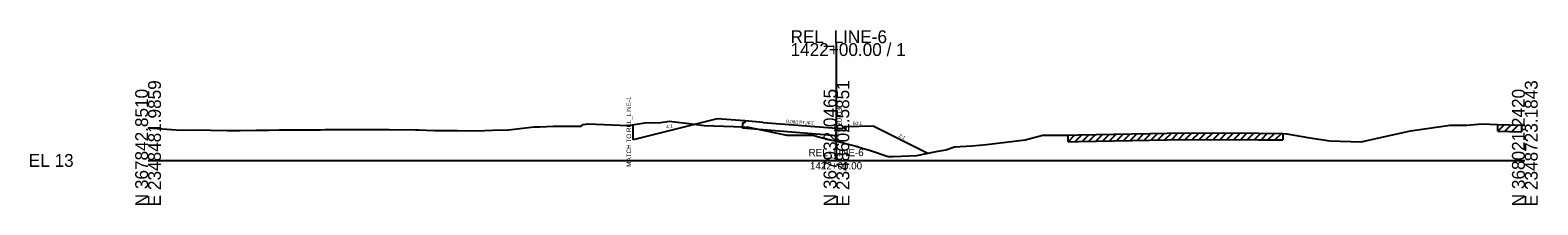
# Model space of a CAD drawing. Extents: x -26 to 403, y -10 to 6565.
# Drawn here: x -25.7 to 302.8, y 2990.3 to 3028.4 of the extents above; entities that cross this region are included whole.
import ezdxf

# ---------------------------------------------------------------- set-up
doc = ezdxf.new("R2010")
doc.units = 0
for name, color, linetype in [('RD_GPK_XS_Cell', 7, 'Continuous'), ('RD_XS_Base', 7, 'Continuous'), ('RD_XS_CurbBase', 7, 'Continuous'), ('RD_XS_CurbFront', 7, 'Continuous'), ('RD_XS_CurbTop', 7, 'Continuous'), ('RD_XS_EarthShd', 7, 'Continuous'), ('RD_XS_ExGround', 7, 'Continuous'), ('RD_XS_ExPaveRet', 7, 'Continuous'), ('RD_XS_Pave', 7, 'Continuous'), ('RD_XS_PaveShd', 7, 'Continuous'), ('RD_XS_TieSlope', 7, 'Continuous'), ('RD_XS_TX_Elev_EX', 7, 'Continuous'), ('RD_XS_TX_Elev_PR', 7, 'Continuous'), ('RD_XS_TX_MatchLine', 7, 'Continuous'), ('RD_XS_TX_Slope', 7, 'Continuous'), ('RD_XS_TX_Station', 7, 'Continuous'), ('RD_XS_TX_TOC', 7, 'Continuous')]:
    doc.layers.add(name, color=color, linetype=linetype)

msp = doc.modelspace()

# ---------------------------------------------------------------- linework, layer by layer
at = {"layer": 'RD_GPK_XS_Cell'}
for p, q in [((150, 3000), (150, 3025.58)), ((0, 3000), (150, 3000)), ((150, 3000), (300, 3000))]:
    msp.add_line(p, q, dxfattribs=at)
at = {"layer": 'RD_XS_Base'}
for p, q in [((130.01, 3008.18), (129.51, 3008.22)), ((129.51, 3008.22), (129.51, 3007.03)), ((150.01, 3005.39), (129.51, 3007.03)), ((130.01, 3008.63), (130.01, 3008.18))]:
    msp.add_line(p, q, dxfattribs=at)
at = {"layer": 'RD_XS_CurbBase'}
for p, q in [((151.51, 3006.43), (150.01, 3006.51)), ((150.01, 3005.39), (150.01, 3006.51)), ((152.01, 3006.43), (151.51, 3006.43)), ((152.01, 3007.43), (152.01, 3006.43))]:
    msp.add_line(p, q, dxfattribs=at)
at = {"layer": 'RD_XS_CurbFront'}
msp.add_line((150.01, 3006.51), (150.01, 3007.01), dxfattribs=at)
at = {"layer": 'RD_XS_CurbTop'}
for p, q in [((150.01, 3007.03), (150.01, 3007.01)), ((150.01, 3007.01), (151.42, 3006.93)), ((151.42, 3006.93), (151.51, 3007.43)), ((151.51, 3007.43), (152.01, 3007.43))]:
    msp.add_line(p, q, dxfattribs=at)
at = {"layer": 'RD_XS_EarthShd'}
for p, q in [((124.01, 3009.11), (105.68, 3004.53)), ((130.01, 3008.63), (124.01, 3009.11)), ((152.01, 3007.43), (158.01, 3007.55))]:
    msp.add_line(p, q, dxfattribs=at)
at = {"layer": 'RD_XS_ExGround'}
msp.add_lwpolyline([(0, 3007.14), (6.15, 3006.7), (8.46, 3006.59), (10.1, 3006.64), (17.24, 3006.5), (20.07, 3006.5), (23.55, 3006.61), (23.86, 3006.61), (24.23, 3006.61), (24.65, 3006.62), (25.13, 3006.62), (25.69, 3006.63), (26.33, 3006.63), (28.56, 3006.64), (29.08, 3006.65), (29.66, 3006.65), (30.33, 3006.66), (31.07, 3006.67), (31.9, 3006.67), (32.81, 3006.68), (33.79, 3006.69), (34.58, 3006.7), (35.48, 3006.7), (35.8, 3006.7), (36.34, 3006.7), (36.92, 3006.71), (37.6, 3006.71), (38.57, 3006.72), (39.79, 3006.72), (40.87, 3006.73), (41.96, 3006.74), (42.63, 3006.75), (43, 3006.76), (43.51, 3006.76), (43.93, 3006.77), (45.04, 3006.78), (45.54, 3006.78), (46.34, 3006.78), (47.07, 3006.78), (47.71, 3006.77), (48.6, 3006.77), (49.4, 3006.77), (50.12, 3006.76), (50.75, 3006.76), (51.31, 3006.75), (51.79, 3006.75), (52.21, 3006.74), (52.56, 3006.73), (58.28, 3006.71), (58.93, 3006.71), (62.45, 3006.53), (67.41, 3006.51), (71.63, 3006.46), (75.05, 3006.63), (78.52, 3006.69), (84.16, 3007.32), (84.56, 3007.33), (84.97, 3007.34), (85.38, 3007.35), (88.33, 3007.49), (91.45, 3007.47), (93.39, 3007.47), (94.36, 3007.47), (94.8, 3007.82), (95.41, 3007.91), (95.82, 3007.97), (104.56, 3007.61), (108.28, 3008.2), (111.76, 3008.31), (113.53, 3008.53), (117.82, 3008.09), (121.21, 3007.65), (127.64, 3007.42), (130.86, 3007.24), (136.33, 3006.08), (137.08, 3005.94), (139.19, 3005.53), (143.23, 3005.52), (144.85, 3005.48), (146.7, 3004.98), (148.62, 3004.52), (150, 3004.17), (154.32, 3003.08), (155.86, 3002.63), (156.7, 3002.42), (157.43, 3002.19), (161.3, 3000.87), (162.41, 3000.89), (167.51, 3001.11), (172.11, 3002.01), (173.84, 3002.3), (175.73, 3002.95), (179.52, 3003.18), (181.15, 3003.3), (182.73, 3003.47), (191.11, 3004.49), (193.32, 3005.08), (194.94, 3005.5), (199.99, 3005.53), (200.52, 3005.53), (202.71, 3005.57), (222.05, 3005.95), (224.62, 3006), (241.99, 3005.92), (247.3, 3005.9), (248.14, 3005.83), (252.75, 3005.03), (257.54, 3004.28), (264.37, 3004.08), (265.31, 3004.29), (275.11, 3006.46), (280.19, 3007.22), (283.77, 3007.72), (287.44, 3007.72), (290.65, 3007.97), (294.15, 3007.86), (299.19, 3007.69), (300, 3007.67)], dxfattribs=at)
at = {"layer": 'RD_XS_ExPaveRet'}
for p, q in [((294.15, 3006.42), (294.15, 3007.86)), ((294.15, 3006.42), (295.54, 3007.81)), ((294.15, 3006.42), (299.19, 3006.25)), ((295.65, 3006.37), (297.04, 3007.76)), ((297.15, 3006.32), (298.54, 3007.71)), ((299.19, 3006.25), (299.28, 3006.25)), ((299.28, 3007.69), (299.28, 3006.25)), ((200.52, 3004.09), (201.98, 3005.56)), ((200.52, 3004.09), (200.52, 3005.53)), ((200.52, 3004.09), (202.71, 3004.13)), ((202.02, 3004.12), (203.48, 3005.59)), ((202.71, 3004.13), (222.05, 3004.51)), ((203.52, 3004.15), (204.98, 3005.62)), ((205.02, 3004.18), (206.48, 3005.64)), ((206.52, 3004.21), (207.98, 3005.67)), ((208.02, 3004.24), (209.48, 3005.7)), ((209.52, 3004.27), (210.98, 3005.73)), ((211.02, 3004.3), (212.48, 3005.76)), ((212.52, 3004.32), (213.98, 3005.79)), ((214.02, 3004.35), (215.48, 3005.82)), ((215.52, 3004.38), (216.98, 3005.85)), ((217.02, 3004.41), (218.48, 3005.88)), ((218.52, 3004.44), (219.98, 3005.91)), ((220.02, 3004.47), (221.48, 3005.94)), ((221.52, 3004.5), (222.98, 3005.97)), ((222.05, 3004.51), (224.62, 3004.56)), ((223.02, 3004.53), (224.49, 3006)), ((224.52, 3004.56), (225.95, 3005.99)), ((224.62, 3004.56), (241.99, 3004.49)), ((226.02, 3004.56), (227.45, 3005.99)), ((227.52, 3004.55), (228.95, 3005.98)), ((229.02, 3004.54), (230.45, 3005.97)), ((230.52, 3004.54), (231.95, 3005.97)), ((232.02, 3004.53), (233.45, 3005.96)), ((233.52, 3004.52), (234.95, 3005.95)), ((235.02, 3004.52), (236.45, 3005.95)), ((236.52, 3004.51), (237.95, 3005.94)), ((238.02, 3004.5), (239.45, 3005.94)), ((239.52, 3004.5), (240.95, 3005.93)), ((241.02, 3004.49), (242.45, 3005.92)), ((241.99, 3004.49), (247.3, 3004.46)), ((242.52, 3004.48), (243.95, 3005.92)), ((244.02, 3004.48), (245.45, 3005.91)), ((245.52, 3004.47), (246.95, 3005.9)), ((247.3, 3005.9), (247.3, 3004.46))]:
    msp.add_line(p, q, dxfattribs=at)
at = {"layer": 'RD_XS_Pave'}
for p, q in [((105.68, 3004.53), (105.68, 3007.79)), ((134.01, 3008.31), (150.01, 3007.03))]:
    msp.add_line(p, q, dxfattribs=at)
at = {"layer": 'RD_XS_PaveShd'}
msp.add_line((134.01, 3008.31), (130.01, 3008.63), dxfattribs=at)
at = {"layer": 'RD_XS_TieSlope'}
msp.add_line((158.01, 3007.55), (169.94, 3001.58), dxfattribs=at)

# ---------------------------------------------------------------- texts
at = {"layer": 'RD_GPK_XS_Cell'}
for s, p in [('REL_LINE-6', (140, 3025.58)), ('1422+00.00 / 1', (140, 3022.78)), ('EL 13', (-26, 2998.6))]:
    msp.add_text(s, height=2.8, dxfattribs=at).set_placement(p)
for s, p in [('E 2348481.9859', (2.8, 2990)), ('E 2348602.5851', (152.8, 2990)), ('E 2348723.1843', (302.8, 2990)), ('N 367842.8510', (0, 2990)), ('N 367932.0465', (150, 2990)), ('N 368021.2420', (300, 2990))]:
    msp.add_text(s, height=2.8, rotation=90, dxfattribs=at).set_placement(p)
at = {"layer": 'RD_XS_TX_Elev_EX'}
msp.add_text('17.17', height=1, rotation=90, dxfattribs=at).set_placement((150.5, 3004.17))
at = {"layer": 'RD_XS_TX_Elev_PR'}
msp.add_text(' 20.03', height=1.2, rotation=90, dxfattribs=at).set_placement((151.2, 3007.03))
at = {"layer": 'RD_XS_TX_MatchLine'}
msp.add_text('MATCH TO REL_LINE-1', height=1, rotation=90, dxfattribs=at).set_placement((105.26, 2998.6))
at = {"layer": 'RD_XS_TX_Slope'}
for s, rotation, p in [('4:1', 14.0362, (112.99, 3006.89)), ('0.080 FT./FT.', 355.4298, (139.01, 3008.16)), ('50:1', 1.1458, (153.58, 3007.68)), ('2:1', 333.4349, (163.5, 3005.18))]:
    msp.add_text(s, height=0.75, rotation=rotation, dxfattribs=at).set_placement(p)
at = {"layer": 'RD_XS_TX_Station'}
for s, p in [('REL_LINE-6', (143.92, 3000.93)), ('1422+00.00', (144.23, 2998.03))]:
    msp.add_text(s, height=1.6, dxfattribs=at).set_placement(p)
at = {"layer": 'RD_XS_TX_TOC'}
msp.add_text('TOCRT', height=0.05, dxfattribs=at).set_placement((151.22, 3007.38))

doc.saveas('drawing.dxf')
